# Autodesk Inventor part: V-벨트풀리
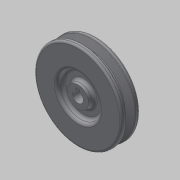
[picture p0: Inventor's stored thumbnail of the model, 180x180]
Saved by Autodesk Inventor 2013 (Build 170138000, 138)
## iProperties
Created: 2015-02
Part Number: V-벨트풀리
Material: 일반
Document SubType Name: Modeling
Designer: Administrator
Density: 1 g/cm^3
Author: Administrator
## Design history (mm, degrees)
sketch "스케치1"
  geometry: L1 (-12.5, 0)-(12.5, 0); L2 (-12.5, 0)-(-12.5, 11); L3 (-12.5, 11)-(-6.5, 11); L4 (-6.5, 11)-(-6.5, 21.5); L5 (-6.5, 21.5)-(-12.5, 21.5); L6 (-12.5, 21.5)-(-12.5, 45.2); L7 (-12.5, 45.2)-(-7.825, 45.2); L8 (-7.825, 45.2)-(-5.074, 36.2); L9 (-5.074, 36.2)-(-0.926, 36.2); L10 (-0.926, 36.2)-(1.825, 45.2); L11 (1.825, 45.2)-(6.5, 45.2); L12 (6.5, 45.2)-(6.5, 21.5); L13 (6.5, 21.5)-(0.5, 21.5); L14 (0.5, 21.5)-(0.5, 11); L15 (0.5, 11)-(12.5, 11); L16 (12.5, 11)-(12.5, 0); L17 (-7, 42.5)-(1, 42.5); L18 (-3, 42.5)-(-3, 36.2); 2 further points
  constraints: 36 end point, 9 parallel, 4 equal length, 3 midpoint, 3 perpendicular, 2 point on line, 1 coincident, 1 collinear, 1 horizontal, 1 vertical alignment
  dimensions: "d0" = 25 distance of L1.start L1.end; "d1" = 6 distance between parallel lines of L6 L4; "d2" = 19 distance of L11.end L6.end; "d3" = 6 distance from line of L12.end L14; "d4" = 34 deg angle of L10 L8; "d5" = 43 diameter of L5 L1; "d6" = 43 diameter of L13 L1; "d7" = 22 diameter of L15 L1; "d23" = 2.7 vertical distance of L11.end L17.end; "d24" = 6.3 vertical distance of L9.end L17.end; "d25" = 85 diameter of L17.start L1; "d26" = 6.3 vertical distance of L8.end L17.start; "d27" = 8 distance of L17.start L17.end
revolve "회전1" sketch "스케치1" stored, may be unused: angle "d28" = 90 deg
sketch "스케치2"
  geometry: L1 (0, 0)-(0, -7.3); L2 (0, -7.3)-(-2, -7.3); L3 (-2, -7.3)-(-2, -5.123); L4 (0, -7.3)-(2, -7.3); L5 (2, -7.3)-(2, -5.123); C1 r 11 at (0, 0) reference; A1 r 5.5 centre (0, 0) between (2, -5.123) and (-2, -5.123)
  constraints: 10 end point, 4 perpendicular, 2 point on circle, 1 centre point, 1 coincident, 1 vertical
  dimensions: "d29" = 11 diameter of A1; "d30" = 7.3 distance of L1.start L1.end; "d31" = 2 distance of L1.end L2.end; "d32" = 2 distance of L1.end L4.end
extrude "돌출1" cut sketch "스케치2" stored distance "d33" = 10; taper "d34" = 0 deg
fillet "모깎기1" dims "d35" = 1, "d36" = 0.5, "d37" = 2
fillet "모깎기2" dims "d38" = 3
node "솔리드1"
